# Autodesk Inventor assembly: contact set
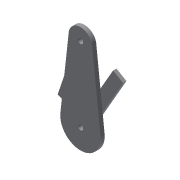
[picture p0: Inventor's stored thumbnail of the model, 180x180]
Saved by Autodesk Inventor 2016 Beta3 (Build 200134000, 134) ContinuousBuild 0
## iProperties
Created: 2016-03
Part Number: contact set
Document SubType Name: Assembly
Designer: Gaurav
Author: Gaurav
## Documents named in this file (3)
- D:\My Data\Books_Final Books\Autodesk Inventor 2015_resources\Chapter 7\Contact_set\contact set.iam
- D:\My Data\Books_Final Books\Autodesk Inventor 2015_resources\Chapter 7\Contact_set\Base.ipt
- D:\My Data\Books_Final Books\Autodesk Inventor 2015_resources\Chapter 7\Contact_set\Rotor.ipt
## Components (3 placed, 2 different names)
1. Base:1 — Rotational:1, Rotational:2
2. Rotor:1 — Rotational:1
3. Rotor:2 — Rotational:2
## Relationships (2: RevoluteJoint 2)
- Rotational:1 [RevoluteJoint]: Base:1 ↔ Rotor:1
- Rotational:2 [RevoluteJoint]: Base:1 ↔ Rotor:2
